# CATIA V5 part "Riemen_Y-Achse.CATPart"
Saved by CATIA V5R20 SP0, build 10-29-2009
Part number: Riemen_Y-Achse
Bounding box of the stored display mesh (mm): x 0 to 9, y -433 to 433, z -120.998 to 15
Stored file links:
  C:\Users\Andi\Desktop\Offene Projekte\Plasmacutter\Riemen_Y-Achse.CATPart
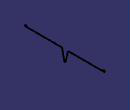
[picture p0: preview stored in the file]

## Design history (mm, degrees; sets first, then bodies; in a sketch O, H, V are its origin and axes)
Body1 (main body)
  Sketch1 on yz-plane, origin (0, 0, 0), H (0, 1, 0), V (0, 0, 1)
    arc A1 centre (0, -112) radius 9 from (-8.7947, -113.9114) to (8.7947, -113.9114) ccw
    point P1 (0, -112)
    line L1 (8.7947, -113.9114) -> (32.1825, -6.301)
    point P4 (33.5519, 0)
    line L2 (40, 0) -> (428, 0)
    line L3 (-8.7947, -113.9114) -> (-32.1825, -6.301)
    point P5 (-33.5519, 0)
    line L4 (-40, 0) -> (-428, 0)
    arc A2 centre (-40, -8) radius 8 from (-32.1825, -6.301) to (-40, 0) ccw
    point P8 (-40, -8)
    arc A3 centre (40, -8) radius 8 from (32.1825, -6.301) to (40, 0) cw
    point P11 (40, -8)
    line L5 (433, 5) -> (433, 13)
    line L6 (431, 15) -> (413, 15)
    point P12 (413, 15)
    line L7 (-433, 5) -> (-433, 13)
    line L8 (-431, 15) -> (-413, 15)
    point P13 (-413, 15)
    arc A4 centre (-428, 5) radius 5 from (-428, 0) to (-433, 5) cw
    arc A5 centre (-431, 13) radius 2 from (-433, 13) to (-431, 15) cw
    arc A6 centre (431, 13) radius 2 from (433, 13) to (431, 15) ccw
    arc A7 centre (428, 5) radius 5 from (428, 0) to (433, 5) ccw
    distance P1 H = 112
    radius A2 = 8
    distance P11 P8 = 80
    radius A1 = 9
    radius A4 = 5
    radius A5 = 2
    distance L8 L4 = 15
    distance P13 L7 = 20
    distance P12 L5 = 20 {= Sketch1.distance(P13 L7)}
    distance L5 L7 = 866
    coincidence: P1 V, P4 H, P5 H, L3 P5, L4 P5, L1 P4, L2 P4
    tangency: L1 A1, L3 A1, A2 L3, A2 L4, A3 L1, A3 L2, A4 L4, A4 L7, A5 L7, A5 L8, A6 L5, A6 L6, A7 L2, A7 L5
    horizontal: L2 H, L4 H, L6 H, L8 H
    symmetry: A3 A2 V, A6 A5 V, A4 A7 V
    vertical: L5 V, L7 V
  Pad1: profile Sketch1, direction (1, 0, 0), length 9, thin wall 2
